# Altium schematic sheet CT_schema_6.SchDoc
size 297 x 271 mm
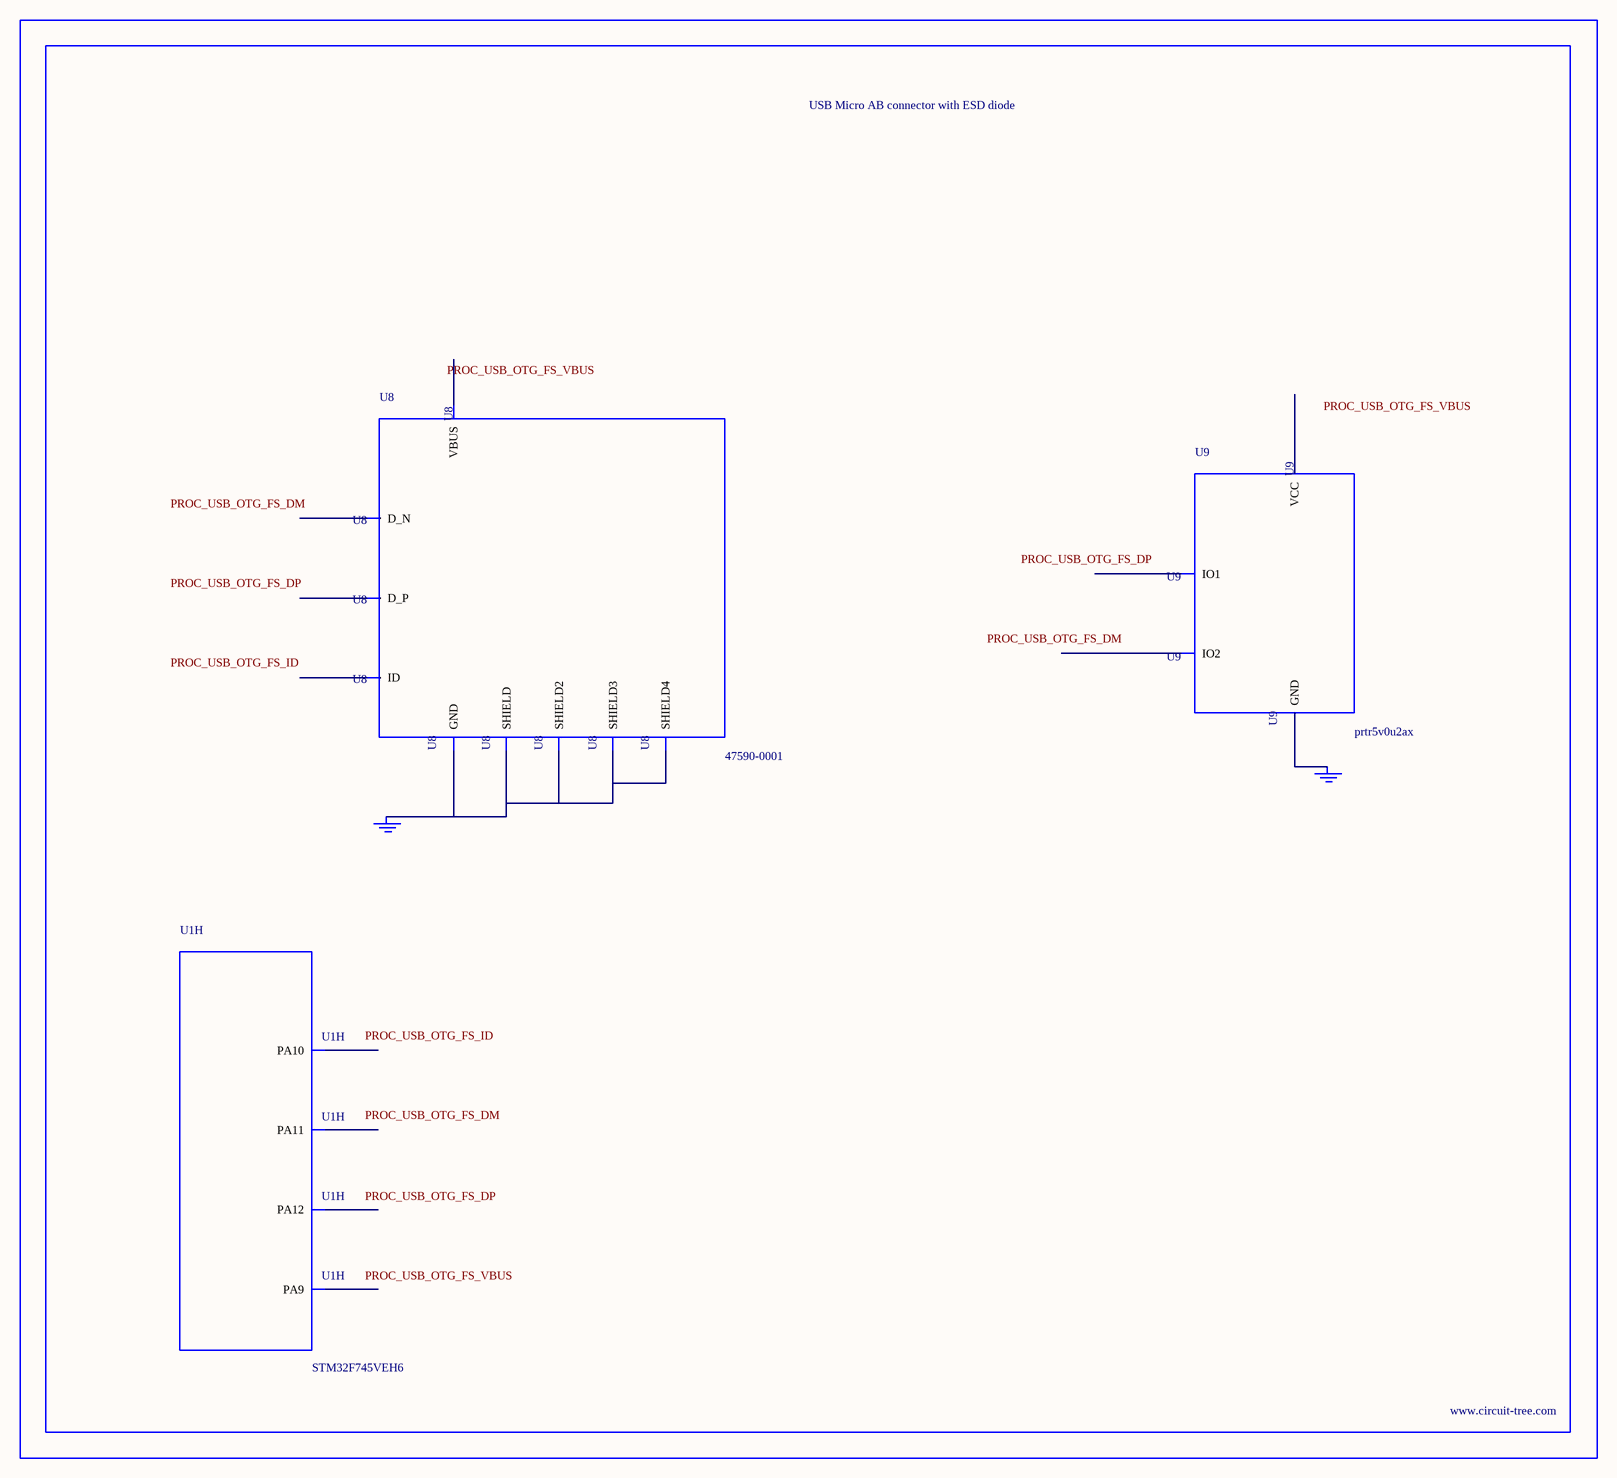
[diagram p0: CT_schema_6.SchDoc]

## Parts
BORDER5  (no value)
GND_INSTANCE_5_0  (no value)
GND_INSTANCE_5_1  (no value)
U1  STM32F745VEH6  [TFBGA100]  (part H of 10)
U8  47590-0001  [MICRO_USB_AB]
U9  prtr5v0u2ax  [SOT143B]

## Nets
NetGND_INSTANCE_5_0_0: GND_INSTANCE_5_0.0(GND) U8.5(GND) U8.6(SHIELD) U8.7(SHIELD2) U8.8(SHIELD3) U8.9(SHIELD4)
NetGND_INSTANCE_5_1_0: GND_INSTANCE_5_1.0(GND) U9.1(GND)

Not connected (* = marked no-connect by the designer): U1 B10(PA12) C9(PA9) C10(PA11) D10(PA10); U8 1(VBUS) 2(D_N) 3(D_P) 4(ID); U9 2(IO1) 3(IO2) 4(VCC)

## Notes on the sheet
- Labels drawn without touching a wire or pin: PROC_USB_OTG_FS_DM, PROC_USB_OTG_FS_DP, PROC_USB_OTG_FS_ID, PROC_USB_OTG_FS_VBUS

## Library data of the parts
BORDER5 = BORDER_PAGE5
GND_INSTANCE_5_0 GND_INSTANCE_5_1 = GND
